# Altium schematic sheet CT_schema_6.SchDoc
size 479 x 328 mm
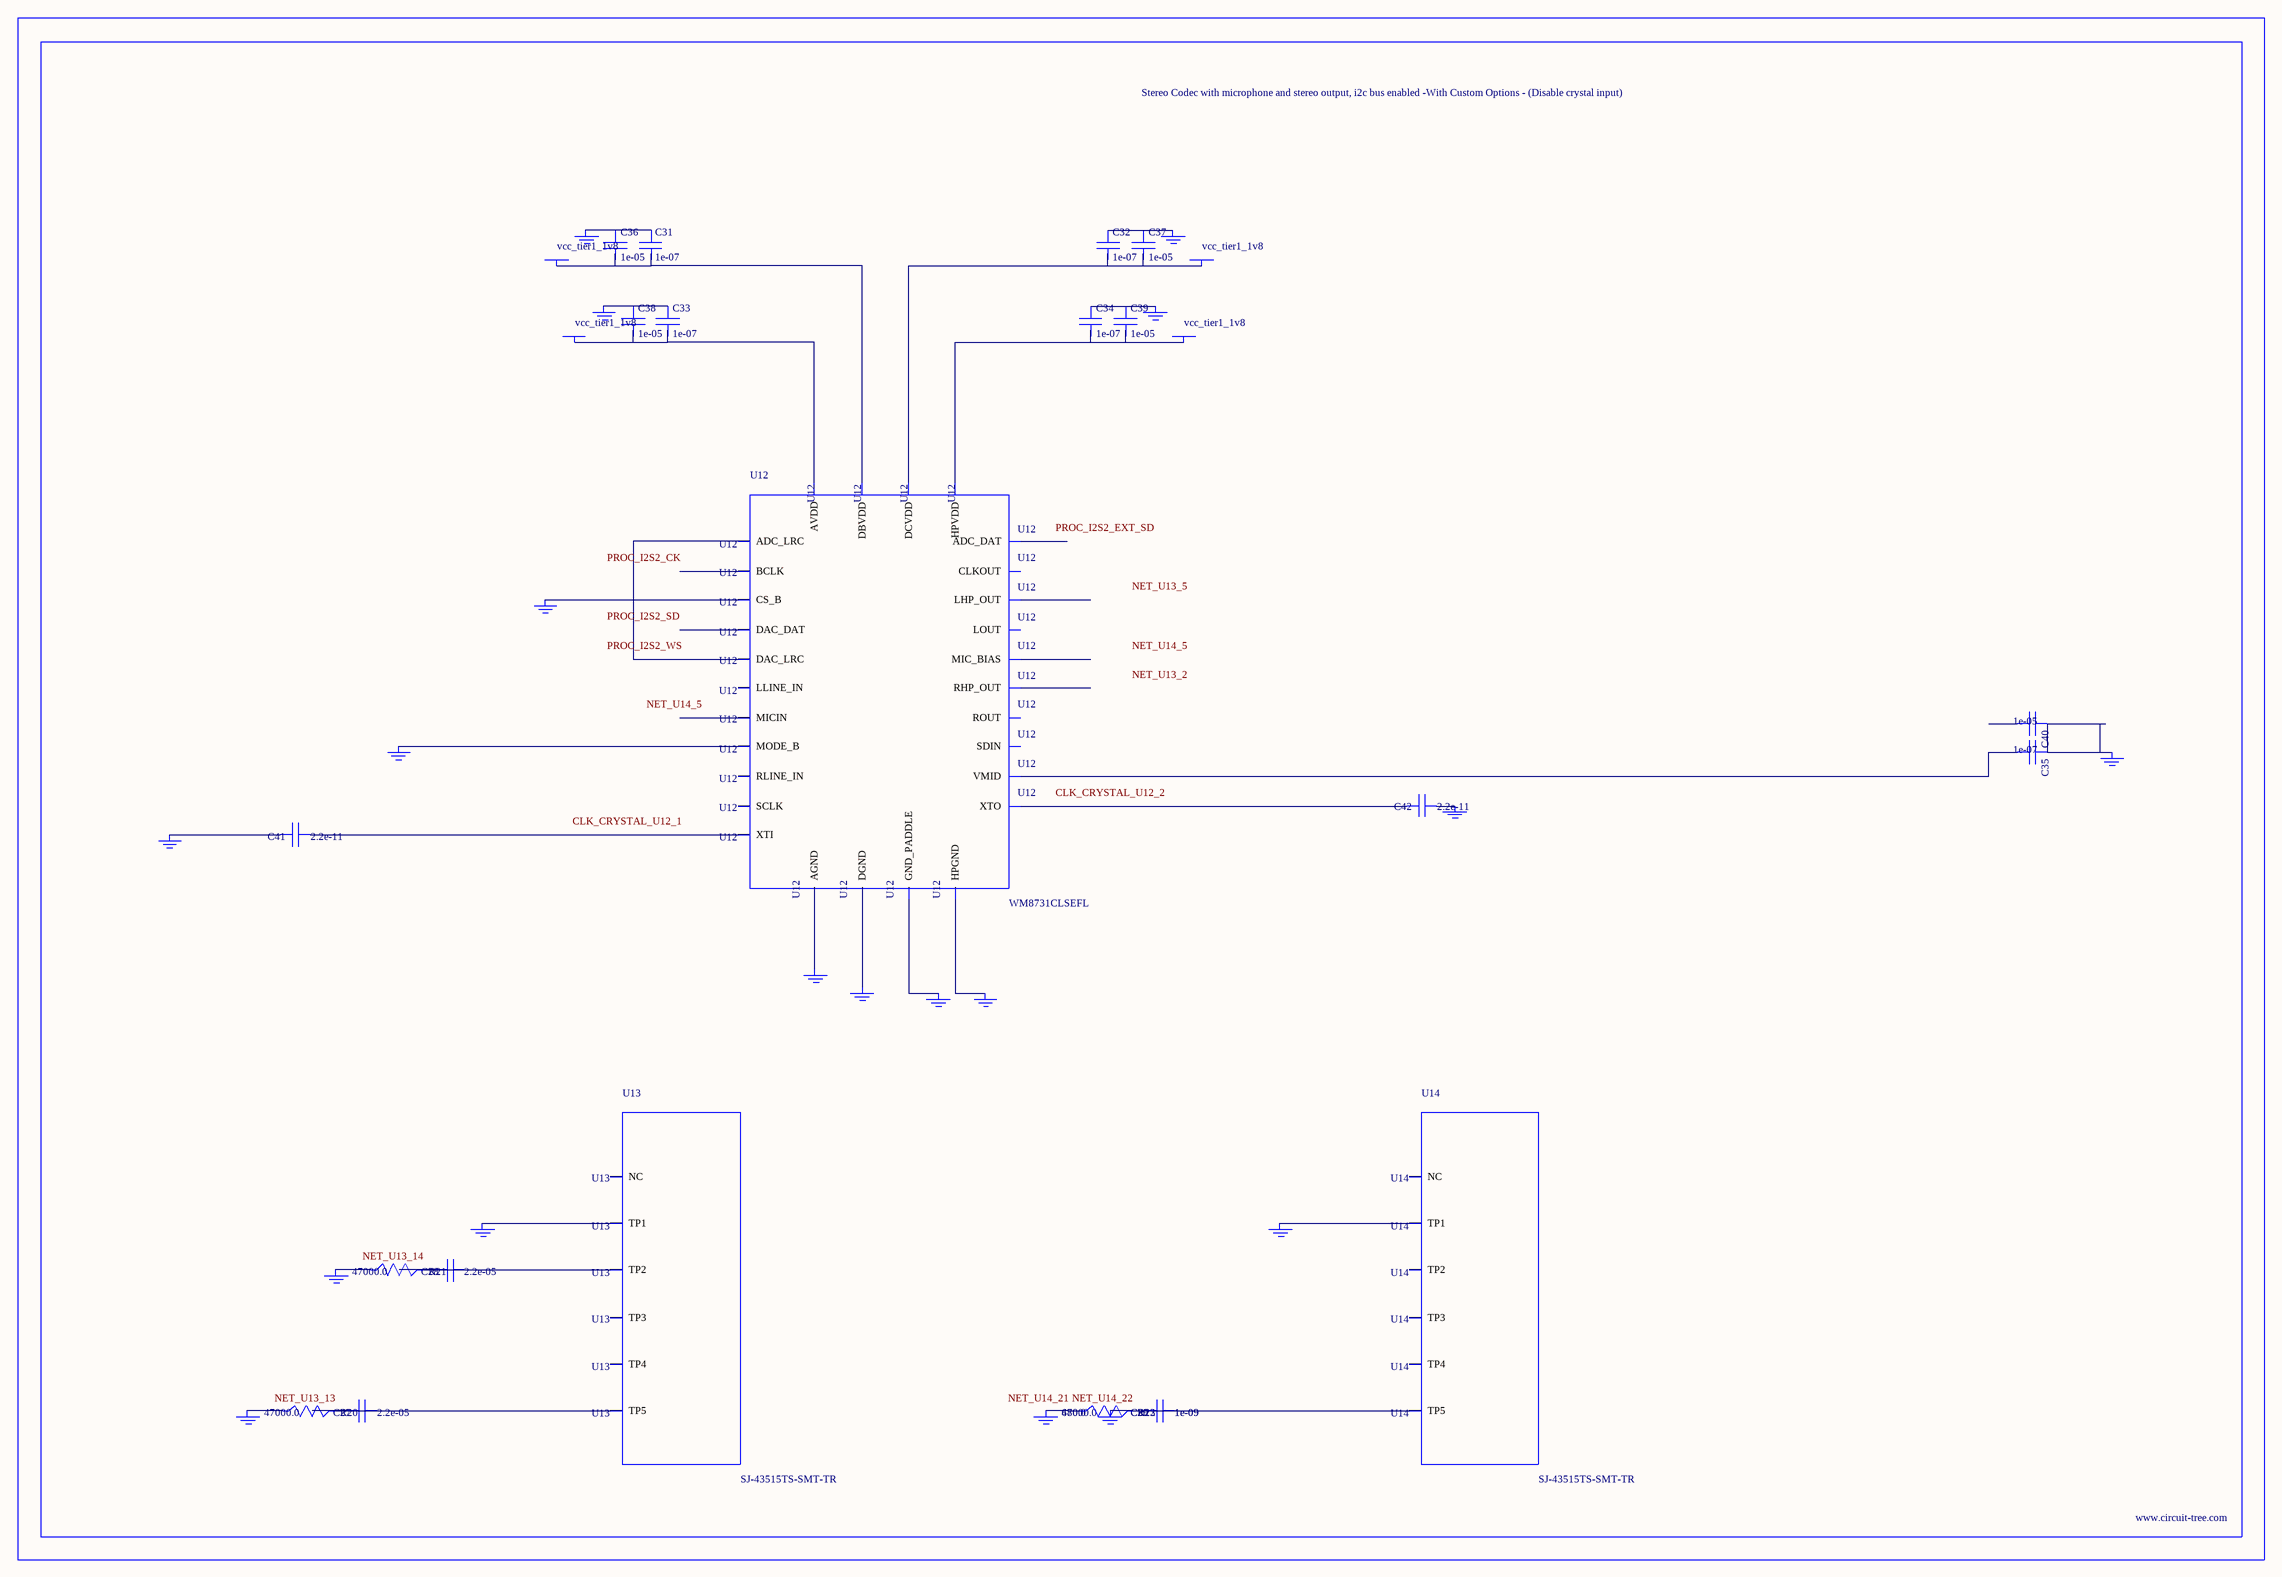
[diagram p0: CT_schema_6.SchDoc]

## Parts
BORDER5  (no value)
C27  2.2e-05  [C1210]
C28  2.2e-05  [C1210]
C29  1e-09  [C0402]
C30  1e-09  [C0402]
C31  1e-07  [C0402]
C32  1e-07  [C0402]
C33  1e-07  [C0402]
C34  1e-07  [C0402]
C35  1e-07  [C0402]
C36  1e-05  [C0805]
C37  1e-05  [C0805]
C38  1e-05  [C0805]
C39  1e-05  [C0805]
C40  1e-05  [C0805]
C41  2.2e-11  [C0402]
C42  2.2e-11  [C0402]
GND_INSTANCE_5_0  (no value)
GND_INSTANCE_5_1  (no value)
GND_INSTANCE_5_2  (no value)
GND_INSTANCE_5_3  (no value)
GND_INSTANCE_5_4  (no value)
GND_INSTANCE_5_5  (no value)
GND_INSTANCE_5_6  (no value)
GND_INSTANCE_5_7  (no value)
GND_INSTANCE_5_8  (no value)
GND_INSTANCE_5_9  (no value)
GND_INSTANCE_5_10  (no value)
GND_INSTANCE_5_11  (no value)
GND_INSTANCE_5_12  (no value)
GND_INSTANCE_5_13  (no value)
GND_INSTANCE_5_14  (no value)
GND_INSTANCE_5_15  (no value)
GND_INSTANCE_5_16  (no value)
GND_INSTANCE_5_17  (no value)
GND_INSTANCE_5_18  (no value)
POWER_INSTANCE_5_0  vcc_tier1_1v8
POWER_INSTANCE_5_1  vcc_tier1_1v8
POWER_INSTANCE_5_2  vcc_tier1_1v8
POWER_INSTANCE_5_3  vcc_tier1_1v8
R20  47000.0  [R0603]
R21  47000.0  [R0603]
R22  47000.0  [R0603]
R23  680.0  [R0603]
U12  WM8731CLSEFL  [QFN-28]
U13  SJ-43515TS-SMT-TR  [SJ-43515TS-SMT-TR]
U14  SJ-43515TS-SMT-TR  [SJ-43515TS-SMT-TR]

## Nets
NetC27_1: C27.1 C27.2 R20.2 U13.5(TP5)
NetC28_1: C28.1 C28.2 R21.2 U13.2(TP2)
NetC29_1: C29.1 C29.2 C30.1 C30.2 GND_INSTANCE_5_18.0(GND) R22.2 R23.2 U14.5(TP5)
NetC31_1: C31.1 C36.1 GND_INSTANCE_5_3.0(GND)
NetC31_2: C31.2 C36.2 POWER_INSTANCE_5_1.0(PWR) U12.5(DBVDD)
NetC32_1: C32.1 C37.1 GND_INSTANCE_5_2.0(GND)
NetC32_2: C32.2 C37.2 POWER_INSTANCE_5_0.0(PWR) U12.3(DCVDD)
NetC33_1: C33.1 C38.1 GND_INSTANCE_5_6.0(GND)
NetC33_2: C33.2 C38.2 POWER_INSTANCE_5_3.0(PWR) U12.18(AVDD)
NetC34_1: C34.1 C39.1 GND_INSTANCE_5_4.0(GND)
NetC34_2: C34.2 C39.2 POWER_INSTANCE_5_2.0(PWR) U12.12(HPVDD)
NetC35_1: C35.1 C40.1 GND_INSTANCE_5_7.0(GND)
NetC35_2: C35.2 U12.20(VMID)
NetC41_1: C41.1 U12.1(XTI)
NetC41_2: C41.2 GND_INSTANCE_5_0.0(GND)
NetC42_1: C42.1 GND_INSTANCE_5_1.0(GND)
NetC42_2: C42.2 U12.2(XTO)
NetGND_INSTANCE_5_5_0: GND_INSTANCE_5_5.0(GND) U12.15(HPGND)
NetGND_INSTANCE_5_8_0: GND_INSTANCE_5_8.0(GND) U12.25(MODE_B)
NetGND_INSTANCE_5_9_0: GND_INSTANCE_5_9.0(GND) U12.26(CS_B)
NetGND_INSTANCE_5_10_0: GND_INSTANCE_5_10.0(GND) U12.29(GND_PADDLE)
NetGND_INSTANCE_5_11_0: GND_INSTANCE_5_11.0(GND) U12.4(DGND)
NetGND_INSTANCE_5_12_0: GND_INSTANCE_5_12.0(GND) U12.19(AGND)
NetGND_INSTANCE_5_13_0: GND_INSTANCE_5_13.0(GND) U13.1(TP1)
NetGND_INSTANCE_5_14_0: GND_INSTANCE_5_14.0(GND) R21.1
NetGND_INSTANCE_5_15_0: GND_INSTANCE_5_15.0(GND) R20.1
NetGND_INSTANCE_5_16_0: GND_INSTANCE_5_16.0(GND) U14.1(TP1)
NetGND_INSTANCE_5_17_0: GND_INSTANCE_5_17.0(GND) R22.1 R23.1
NetU12_9: U12.9(DAC_LRC) U12.11(ADC_LRC)

Not connected (* = marked no-connect by the designer): C40 2; U12 6(CLKOUT) 7(BCLK) 8(DAC_DAT) 10(ADC_DAT) 13(LHP_OUT) 14(RHP_OUT) 16(LOUT) 17(ROUT) 21(MIC_BIAS) 22(MICIN) 23(RLINE_IN) 24(LLINE_IN) 27(SDIN) 28(SCLK); U13 3(TP3) 4(TP4) 6(NC); U14 2(TP2) 3(TP3) 4(TP4) 6(NC)

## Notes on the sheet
- Labels drawn without touching a wire or pin: CLK_CRYSTAL_U12_1, CLK_CRYSTAL_U12_2, NET_U13_2, NET_U13_5, NET_U13_13, NET_U13_14, NET_U14_5, NET_U14_21, NET_U14_22, PROC_I2S2_CK, PROC_I2S2_EXT_SD, PROC_I2S2_SD, PROC_I2S2_WS

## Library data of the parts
BORDER5 = BORDER_PAGE5
C27 C28 = C1210C224K5RACTU
C29 C30 = C0402C102K3RAC
C31-C35 = C0402C104K3RACTU
C36-C40 = C0805C106K8RACTU
C41 C42 = C0402C220K3RAC
GND_INSTANCE_5_0-GND_INSTANCE_5_18 = GND
POWER_INSTANCE_5_0-POWER_INSTANCE_5_3 = PWR
R20-R22 = RC0603JR-0747KL
R23 = RC0603JR-07680RL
